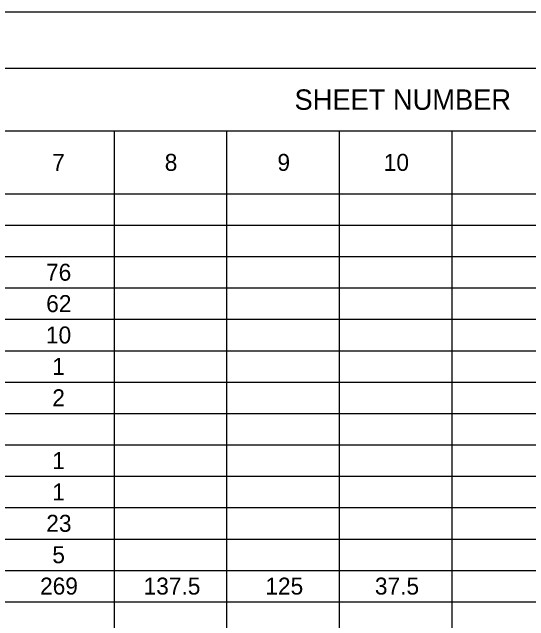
# Model space of a CAD drawing. Extents: x 0 to 34, y 0 to 22.
# Drawn here: x 4.61 to 9.22, y 16.57 to 22 of the extents above; entities that cross this region are included whole.
import ezdxf

# ---------------------------------------------------------------- set-up
doc = ezdxf.new("R2010")
doc.units = 0
for name, color, linetype in [('SH_Border', 7, 'Continuous'), ('SH_Cut_Line', 7, 'Continuous'), ('SH_Text', 7, 'Continuous')]:
    doc.layers.add(name, color=color, linetype=linetype)

msp = doc.modelspace()

# ---------------------------------------------------------------- linework, layer by layer
at = {"layer": 'SH_Border'}
msp.add_lwpolyline([(1.5, 21.5), (33.5, 21.5), (33.5, 0.5), (1.5, 0.5)], close=True, dxfattribs=at)
at = {"layer": 'SH_Cut_Line'}
msp.add_lwpolyline([(0, 0), (34, 0), (34, 22), (0, 22)], close=True, dxfattribs=at)
at = {"layer": 'SH_Text'}
for p, q in [((1.5, 21.5), (32.0035, 21.5)), ((1.5, 20.94), (15.5659, 20.94)), ((5.5188, 20.94), (5.5188, 0.5)), ((6.5235, 20.94), (6.5235, 0.5)), ((7.5282, 20.94), (7.5282, 0.5)), ((8.5329, 20.94), (8.5329, 0.5)), ((1.5, 20.38), (32.0035, 20.38)), ((1.5, 20.1), (32.0035, 20.1)), ((1.5, 19.82), (32.0035, 19.82)), ((1.5, 19.54), (32.0035, 19.54)), ((1.5, 19.26), (32.0035, 19.26)), ((1.5, 18.98), (32.0035, 18.98)), ((1.5, 18.7), (32.0035, 18.7)), ((1.5, 18.42), (32.0035, 18.42)), ((1.5, 18.14), (32.0035, 18.14)), ((1.5, 17.86), (32.0035, 17.86)), ((1.5, 17.58), (32.0035, 17.58)), ((1.5, 17.3), (32.0035, 17.3)), ((1.5, 17.02), (32.0035, 17.02)), ((1.5, 16.74), (32.0035, 16.74))]:
    msp.add_line(p, q, dxfattribs=at)

# ---------------------------------------------------------------- texts
for s, height, p in [('SHEET NUMBER', 0.181835, (7.1295, 21.1291)), ('7', 0.1515, (4.967, 20.5842)), ('8', 0.1515, (5.9712, 20.5842)), ('9', 0.1515, (6.9769, 20.5842)), ('10', 0.15153, (7.9255, 20.5842)), ('76', 0.15153, (4.9119, 19.6042)), ('62', 0.15153, (4.9136, 19.3242)), ('10', 0.15153, (4.9113, 19.0442)), ('1', 0.1515, (4.9679, 18.7642)), ('2', 0.1515, (4.968, 18.4842)), ('1', 0.1515, (4.9679, 17.9242)), ('1', 0.1515, (4.9679, 17.6442)), ('23', 0.15153, (4.9142, 17.3642)), ('5', 0.1515, (4.9683, 17.0842)), ('269', 0.15153, (4.8586, 16.8042)), ('137.5', 0.15153, (5.7826, 16.8042)), ('125', 0.15153, (6.8689, 16.8042)), ('37.5', 0.15153, (7.8464, 16.8042))]:
    msp.add_text(s, height=height, dxfattribs=at).set_placement(p)

doc.saveas('drawing.dxf')
